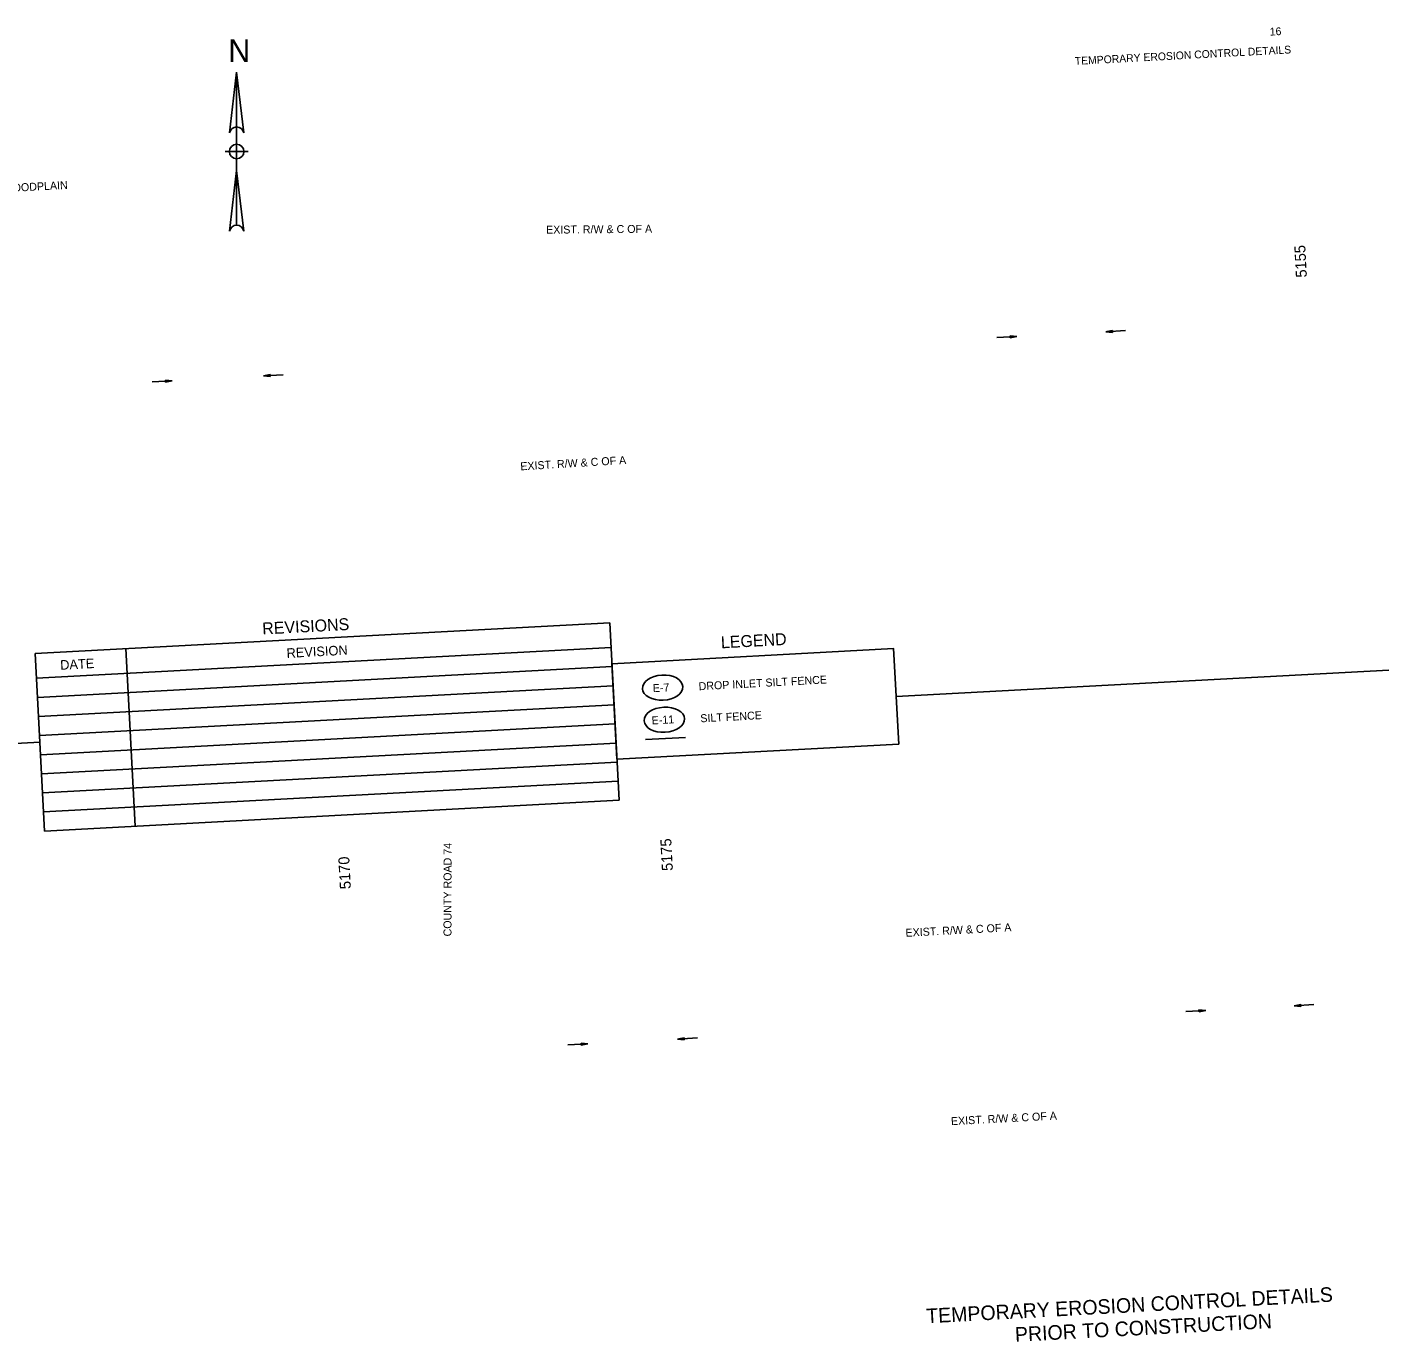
# Model space of a CAD drawing. Extents: x 257063 to 260260, y 223752 to 225802.
# Drawn here: x 258210 to 260260, y 223752 to 225732 of the extents above; entities that cross this region are included whole.
import ezdxf

# ---------------------------------------------------------------- set-up
doc = ezdxf.new("R2010")
doc.units = 0
for name, color, linetype in [('24X36', 7, 'Continuous'), ('DRAINAGE ARROWS', 7, 'Continuous'), ('Level 1', 7, 'Continuous'), ('Level 15', 7, 'Continuous'), ('Level 2', 7, 'Continuous'), ('Level 24', 7, 'Continuous'), ('Level 30', 7, 'Continuous'), ('R_Water Annot', 7, 'Continuous'), ('STATIONING1', 7, 'Continuous')]:
    doc.layers.add(name, color=color, linetype=linetype)

msp = doc.modelspace()

# ---------------------------------------------------------------- linework, layer by layer
at = {"layer": '24X36'}
msp.add_line((259140.6, 224658.7), (259201.1, 224661.9), dxfattribs=at)
at = {"layer": 'DRAINAGE ARROWS'}
for p, q in [((259689.7, 225266.8), (259699.8, 225265.8)), ((259689.9, 225263.8), (259689.7, 225266.8)), ((259689.7, 225266.5), (259698.1, 225265.7)), ((259689.7, 225266.3), (259696.4, 225265.6)), ((259689.8, 225266), (259694.7, 225265.5)), ((259689.8, 225265.8), (259693, 225265.4)), ((259689.8, 225264.3), (259696.4, 225265.6)), ((259689.8, 225264.5), (259694.7, 225265.5)), ((259689.8, 225265.5), (259691.4, 225265.3)), ((259689.8, 225264.8), (259693, 225265.4)), ((259689.8, 225265), (259691.4, 225265.3)), ((259689.9, 225263.8), (259699.8, 225265.8)), ((259689.9, 225264), (259698.1, 225265.7)), ((259843.6, 225275), (259833.7, 225273)), ((259843.7, 225272), (259833.7, 225273)), ((259843.6, 225274.8), (259835.3, 225273.1)), ((259843.7, 225272.3), (259835.3, 225273.1)), ((259843.6, 225274.5), (259837.1, 225273.2)), ((259843.7, 225272.5), (259837.1, 225273.2)), ((259843.6, 225274.3), (259838.7, 225273.3)), ((259843.7, 225272.8), (259838.7, 225273.3)), ((259843.6, 225274), (259840.4, 225273.3)), ((259843.7, 225273), (259840.4, 225273.3)), ((259843.7, 225273.8), (259842.1, 225273.4)), ((259843.7, 225273.3), (259842.1, 225273.4)), ((259843.7, 225272), (259843.6, 225275)), ((258418.1, 225200.1), (258428.1, 225199.1)), ((258418.2, 225197.1), (258418.1, 225200.1)), ((258418.1, 225199.8), (258426.5, 225199)), ((258418.1, 225199.6), (258424.8, 225198.9)), ((258418.1, 225199.3), (258423.1, 225198.8)), ((258418.1, 225199), (258421.4, 225198.7)), ((258418.1, 225198.8), (258419.7, 225198.6)), ((258418.2, 225197.1), (258428.1, 225199.1)), ((258418.2, 225197.3), (258426.5, 225199)), ((258418.2, 225197.6), (258424.8, 225198.9)), ((258418.2, 225197.8), (258423.1, 225198.8)), ((258418.2, 225198.1), (258421.4, 225198.7)), ((258418.2, 225198.3), (258419.7, 225198.6)), ((258575.4, 225208.5), (258565.5, 225206.4)), ((258575.6, 225205.5), (258565.5, 225206.4)), ((258575.4, 225208.3), (258567.1, 225206.5)), ((258575.5, 225205.8), (258567.1, 225206.5)), ((258575.4, 225208), (258568.9, 225206.6)), ((258575.5, 225206), (258568.9, 225206.6)), ((258575.4, 225207.8), (258570.5, 225206.7)), ((258575.5, 225206.3), (258570.5, 225206.7)), ((258575.4, 225207.5), (258572.2, 225206.8)), ((258575.5, 225206.5), (258572.2, 225206.8)), ((258575.5, 225207.2), (258573.9, 225206.9)), ((258575.5, 225206.8), (258573.9, 225206.9)), ((258575.6, 225205.5), (258575.4, 225208.5)), ((260127.1, 224259.9), (260117.2, 224257.9)), ((260127.2, 224256.9), (260117.2, 224257.9)), ((260127.1, 224259.7), (260118.8, 224258)), ((260127.2, 224257.2), (260118.8, 224258)), ((260127.1, 224259.4), (260120.5, 224258.1)), ((260127.2, 224257.5), (260120.5, 224258.1)), ((260127.1, 224259.2), (260122.2, 224258.2)), ((260127.2, 224257.7), (260122.2, 224258.2)), ((260127.1, 224258.9), (260123.9, 224258.3)), ((260127.2, 224258), (260123.9, 224258.3)), ((260127.1, 224258.7), (260125.6, 224258.4)), ((260127.2, 224258.2), (260125.6, 224258.4)), ((260127.2, 224256.9), (260127.1, 224259.9)), ((259974, 224251.7), (259984.1, 224250.7)), ((259974.2, 224248.7), (259974, 224251.7)), ((259974, 224251.5), (259982.4, 224250.7)), ((259974, 224251.2), (259980.7, 224250.6)), ((259974, 224251), (259979, 224250.5)), ((259974.1, 224250.7), (259977.3, 224250.4)), ((259974.1, 224249), (259982.4, 224250.7)), ((259974.1, 224249.2), (259980.7, 224250.6)), ((259974.1, 224249.5), (259979, 224250.5)), ((259974.1, 224250.5), (259975.7, 224250.3)), ((259974.1, 224249.7), (259977.3, 224250.4)), ((259974.1, 224250), (259975.7, 224250.3)), ((259974.2, 224248.7), (259984.1, 224250.7)), ((259043.9, 224201.5), (259053.9, 224200.5)), ((259044, 224198.5), (259043.9, 224201.5)), ((259043.9, 224201.3), (259052.3, 224200.4)), ((259043.9, 224201), (259050.5, 224200.4)), ((259043.9, 224200.8), (259048.9, 224200.3)), ((259043.9, 224200.5), (259047.2, 224200.2)), ((259043.9, 224200.2), (259045.5, 224200.1)), ((259043.9, 224199.8), (259045.5, 224200.1)), ((259044, 224198.5), (259053.9, 224200.5)), ((259044, 224199), (259050.5, 224200.4)), ((259044, 224198.8), (259052.3, 224200.4)), ((259044, 224199.3), (259048.9, 224200.3)), ((259044, 224199.5), (259047.2, 224200.2)), ((259198.9, 224209.8), (259189, 224207.8)), ((259199.1, 224206.8), (259189, 224207.8)), ((259198.9, 224209.6), (259190.7, 224207.9)), ((259199.1, 224207.1), (259190.7, 224207.9)), ((259199, 224209.3), (259192.4, 224208)), ((259199.1, 224207.3), (259192.4, 224208)), ((259199, 224209.1), (259194.1, 224208.1)), ((259199.1, 224207.6), (259194.1, 224208.1)), ((259199, 224208.8), (259195.8, 224208.2)), ((259199, 224207.9), (259195.8, 224208.2)), ((259199, 224208.6), (259197.4, 224208.2)), ((259199, 224208.1), (259197.4, 224208.2)), ((259199.1, 224206.8), (259198.9, 224209.8))]:
    msp.add_line(p, q, dxfattribs=at)
at = {"layer": 'Level 1'}
for p, q in [((258514.3, 225572.7), (258525.2, 225664.1)), ((258525.2, 225664.1), (258536.1, 225572.7)), ((258525.2, 225664.1), (258525.2, 225581.4)), ((258525.2, 225572.7), (258525.2, 225581.4)), ((258525.2, 225572.7), (258525.2, 225555.2)), ((258513.9, 225544.3), (258507.8, 225544.3)), ((258525.2, 225544.3), (258514.7, 225544.3)), ((258525.2, 225555.2), (258525.2, 225544.3)), ((258525.2, 225544.3), (258525.2, 225533.5)), ((258525.2, 225544.3), (258536.1, 225544.3)), ((258525.2, 225533.5), (258525.2, 225544.3)), ((258536.1, 225544.3), (258542.6, 225544.3)), ((258536.1, 225544.3), (258536.1, 225544.3)), ((258525.2, 225533.5), (258525.2, 225516)), ((258525.2, 225516), (258514.3, 225424.6)), ((258525.2, 225433.3), (258525.2, 225516)), ((258525.2, 225516), (258536.1, 225424.6)), ((258221.8, 224788.5), (259086.8, 224834.8)), ((259086.8, 224834.8), (259101.1, 224567.3)), ((258236.1, 224521), (258221.8, 224788.5)), ((258223.8, 224751.1), (259088.8, 224797.4)), ((258358.2, 224795.8), (258372.5, 224528.3)), ((258225.3, 224722.3), (259090.3, 224768.7)), ((259518.1, 224723.8), (260259.7, 224763.5)), ((258226.9, 224693.6), (259091.9, 224739.9)), ((258228.4, 224664.8), (259093.4, 224711.1)), ((258230, 224636), (259095, 224682.4)), ((257063.2, 224592.3), (258229, 224654.7)), ((258231.5, 224607.3), (259096.5, 224653.6)), ((258233, 224578.5), (259098.1, 224624.9)), ((258234.6, 224549.8), (259099.6, 224596.1)), ((259101.1, 224567.3), (258236.1, 224521)), ((259101.1, 224567.3), (259101.1, 224567.3))]:
    msp.add_line(p, q, dxfattribs=at)
msp.add_lwpolyline([(259090.1, 224773), (259514.3, 224795.7), (259522, 224651.9), (259097.8, 224629.2)], close=True, dxfattribs=at)
for centre, radius, start, end in [((258525.2, 225570.2), 11.2, 90, 167.3196), ((258525.2, 225570.2), 11.2, 12.6804, 90), ((258525.2, 225544.4), 10.9, 90, 180), ((258525.2, 225544.4), 10.9, 180, 270), ((258525.2, 225544.4), 10.9, 0, 90), ((258525.2, 225544.4), 10.9, 270, 0), ((258525.2, 225422.2), 11.2, 90, 167.3196), ((258525.2, 225422.2), 11.2, 12.6804, 90)]:
    msp.add_arc(centre, radius, start, end, dxfattribs=at)
at = {"layer": 'Level 30'}
for centre in [(259166.5, 224737), (259169.1, 224688.6)]:
    msp.add_ellipse(centre, major_axis=(30.4, 1.6), ratio=0.622507, dxfattribs=at)
at = {"layer": 'R_Water Annot'}
for p, q in [((259669.8, 225264.2), (259699.8, 225265.8)), ((259689.7, 225266.8), (259699.8, 225265.8)), ((259689.9, 225263.8), (259689.7, 225266.8)), ((259689.7, 225266.5), (259698.1, 225265.7)), ((259689.7, 225266.3), (259696.4, 225265.6)), ((259689.8, 225266), (259694.7, 225265.5)), ((259689.8, 225265.8), (259693, 225265.4)), ((259689.8, 225264.3), (259696.4, 225265.6)), ((259689.8, 225264.5), (259694.7, 225265.5)), ((259689.8, 225265.5), (259691.4, 225265.3)), ((259689.8, 225264.8), (259693, 225265.4)), ((259689.8, 225265), (259691.4, 225265.3)), ((259689.9, 225263.8), (259699.8, 225265.8)), ((259689.9, 225264), (259698.1, 225265.7)), ((259843.6, 225275), (259833.7, 225273)), ((259863.6, 225274.7), (259833.7, 225273)), ((259843.7, 225272), (259833.7, 225273)), ((259843.6, 225274.8), (259835.3, 225273.1)), ((259843.7, 225272.3), (259835.3, 225273.1)), ((259843.6, 225274.5), (259837.1, 225273.2)), ((259843.7, 225272.5), (259837.1, 225273.2)), ((259843.6, 225274.3), (259838.7, 225273.3)), ((259843.7, 225272.8), (259838.7, 225273.3)), ((259843.6, 225274), (259840.4, 225273.3)), ((259843.7, 225273), (259840.4, 225273.3)), ((259843.7, 225273.8), (259842.1, 225273.4)), ((259843.7, 225273.3), (259842.1, 225273.4)), ((259843.7, 225272), (259843.6, 225275)), ((258398.2, 225197.5), (258428.1, 225199.1)), ((258418.1, 225200.1), (258428.1, 225199.1)), ((258418.2, 225197.1), (258418.1, 225200.1)), ((258418.1, 225199.8), (258426.5, 225199)), ((258418.1, 225199.6), (258424.8, 225198.9)), ((258418.1, 225199.3), (258423.1, 225198.8)), ((258418.1, 225199), (258421.4, 225198.7)), ((258418.1, 225198.8), (258419.7, 225198.6)), ((258418.2, 225197.1), (258428.1, 225199.1)), ((258418.2, 225197.3), (258426.5, 225199)), ((258418.2, 225197.6), (258424.8, 225198.9)), ((258418.2, 225197.8), (258423.1, 225198.8)), ((258418.2, 225198.1), (258421.4, 225198.7)), ((258418.2, 225198.3), (258419.7, 225198.6)), ((258575.4, 225208.5), (258565.5, 225206.4)), ((258595.4, 225208.1), (258565.5, 225206.4)), ((258575.6, 225205.5), (258565.5, 225206.4)), ((258575.4, 225208.3), (258567.1, 225206.5)), ((258575.5, 225205.8), (258567.1, 225206.5)), ((258575.4, 225208), (258568.9, 225206.6)), ((258575.5, 225206), (258568.9, 225206.6)), ((258575.4, 225207.8), (258570.5, 225206.7)), ((258575.5, 225206.3), (258570.5, 225206.7)), ((258575.4, 225207.5), (258572.2, 225206.8)), ((258575.5, 225206.5), (258572.2, 225206.8)), ((258575.5, 225207.2), (258573.9, 225206.9)), ((258575.5, 225206.8), (258573.9, 225206.9)), ((258575.6, 225205.5), (258575.4, 225208.5)), ((260127.1, 224259.9), (260117.2, 224257.9)), ((260147.1, 224259.6), (260117.2, 224257.9)), ((260127.2, 224256.9), (260117.2, 224257.9)), ((260127.1, 224259.7), (260118.8, 224258)), ((260127.2, 224257.2), (260118.8, 224258)), ((260127.1, 224259.4), (260120.5, 224258.1)), ((260127.2, 224257.5), (260120.5, 224258.1)), ((260127.1, 224259.2), (260122.2, 224258.2)), ((260127.2, 224257.7), (260122.2, 224258.2)), ((260127.1, 224258.9), (260123.9, 224258.3)), ((260127.2, 224258), (260123.9, 224258.3)), ((260127.1, 224258.7), (260125.6, 224258.4)), ((260127.2, 224258.2), (260125.6, 224258.4)), ((260127.2, 224256.9), (260127.1, 224259.9)), ((259954.1, 224249.2), (259984.1, 224250.7)), ((259974, 224251.7), (259984.1, 224250.7)), ((259974.2, 224248.7), (259974, 224251.7)), ((259974, 224251.5), (259982.4, 224250.7)), ((259974, 224251.2), (259980.7, 224250.6)), ((259974, 224251), (259979, 224250.5)), ((259974.1, 224250.7), (259977.3, 224250.4)), ((259974.1, 224249), (259982.4, 224250.7)), ((259974.1, 224249.2), (259980.7, 224250.6)), ((259974.1, 224249.5), (259979, 224250.5)), ((259974.1, 224250.5), (259975.7, 224250.3)), ((259974.1, 224249.7), (259977.3, 224250.4)), ((259974.1, 224250), (259975.7, 224250.3)), ((259974.2, 224248.7), (259984.1, 224250.7)), ((259024, 224199), (259053.9, 224200.5)), ((259043.9, 224201.5), (259053.9, 224200.5)), ((259044, 224198.5), (259043.9, 224201.5)), ((259043.9, 224201.3), (259052.3, 224200.4)), ((259043.9, 224201), (259050.5, 224200.4)), ((259043.9, 224200.8), (259048.9, 224200.3)), ((259043.9, 224200.5), (259047.2, 224200.2)), ((259043.9, 224200.2), (259045.5, 224200.1)), ((259043.9, 224199.8), (259045.5, 224200.1)), ((259044, 224198.5), (259053.9, 224200.5)), ((259044, 224199), (259050.5, 224200.4)), ((259044, 224198.8), (259052.3, 224200.4)), ((259044, 224199.3), (259048.9, 224200.3)), ((259044, 224199.5), (259047.2, 224200.2)), ((259198.9, 224209.8), (259189, 224207.8)), ((259219, 224209.5), (259189, 224207.8)), ((259199.1, 224206.8), (259189, 224207.8)), ((259198.9, 224209.6), (259190.7, 224207.9)), ((259199.1, 224207.1), (259190.7, 224207.9)), ((259199, 224209.3), (259192.4, 224208)), ((259199.1, 224207.3), (259192.4, 224208)), ((259199, 224209.1), (259194.1, 224208.1)), ((259199.1, 224207.6), (259194.1, 224208.1)), ((259199, 224208.8), (259195.8, 224208.2)), ((259199, 224207.9), (259195.8, 224208.2)), ((259199, 224208.6), (259197.4, 224208.2)), ((259199, 224208.1), (259197.4, 224208.2)), ((259199.1, 224206.8), (259198.9, 224209.8))]:
    msp.add_line(p, q, dxfattribs=at)

# ---------------------------------------------------------------- texts
at = {"layer": 'Level 1'}
for s, height, p in [('16', 11.72, (260080.9, 225718.9)), ('TEMPORARY EROSION CONTROL DETAILS', 11.7, (259787.4, 225674.8)), ('REVISION', 14.4, (258600.7, 224781.7)), ('DATE', 14.4, (258259.9, 224763.8))]:
    msp.add_text(s, height=height, rotation=3.0666, dxfattribs=at).set_placement(p)
msp.add_text('N', height=34.2, dxfattribs=at).set_placement((258512.6, 225679.2))
at = {"layer": 'Level 15'}
msp.add_text('5155', height=16.5, rotation=93.0667, dxfattribs=at).set_placement((260136.5, 225354.9))
at = {"layer": 'Level 2'}
for s, p in [('TEMPORARY EROSION CONTROL DETAILS', (259563.9, 223779.6)), ('PRIOR TO CONSTRUCTION', (259697.5, 223751.7))]:
    msp.add_text(s, height=22, rotation=3.0666, dxfattribs=at).set_placement(p)
at = {"layer": 'Level 24'}
for s, rotation, p in [('100 YR. FLOODPLAIN', 3.0666, (258107.2, 225479.4)), ('EXIST. R/W & C OF A', 0.5307, (258991.1, 225420.6)), ('EXIST. R/W & C OF A', 3.488, (258952.6, 225064.2)), ('COUNTY ROAD 74', 89.9666, (258848.6, 224362.3)), ('EXIST. R/W & C OF A', 3.0666, (259532.5, 224361.7)), ('EXIST. R/W & C OF A', 3.0666, (259600.9, 224078))]:
    msp.add_text(s, height=12, rotation=rotation, dxfattribs=at).set_placement(p)
at = {"layer": 'Level 30'}
for s, height, p in [('REVISIONS', 18, (258564.2, 224816.9)), ('LEGEND', 18, (259254.7, 224796.1)), ('DROP INLET SILT FENCE', 11.997, (259221, 224733)), ('E-7', 12, (259152, 224730.1)), ('E-11', 12, (259150.3, 224681.5)), ('SILT FENCE ', 11.997, (259223.6, 224684.7))]:
    msp.add_text(s, height=height, rotation=3.0666, dxfattribs=at).set_placement(p)
at = {"layer": 'STATIONING1'}
for s, p in [('5175', (259182, 224461.3)), ('5170', (258697.2, 224434))]:
    msp.add_text(s, height=16.5, rotation=93.0667, dxfattribs=at).set_placement(p)

doc.saveas('drawing.dxf')
